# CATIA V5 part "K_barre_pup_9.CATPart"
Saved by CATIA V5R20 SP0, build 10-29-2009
Part number: barre_pup_9
Bounding box of the stored display mesh (mm): x -68.541 to -50.815, y -5.5 to 50.136, z -97.461 to 38.68
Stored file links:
  G:\Khaled_CFAO_2011\ST2M\ST2M_GR2\gcausse\Khaled\CAD_ThinkMotion\K_barre_pup_9.CATPart
  C:\Documents and Settings\gcausse\Bureau\video thinkmotio\assemblage_gcausse\pupitre_think.CATProduct
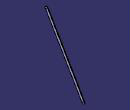
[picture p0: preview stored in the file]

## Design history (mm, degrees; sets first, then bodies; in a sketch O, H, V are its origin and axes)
Set1
  Sketch1 on Plane1, origin (-54.7303, 0, 6.7329), H (0, 1, 0), V (0.1221, 0, 0.9925)
    line L1 (-0.6657, 30.4606) -> (49.9709, -101.5846)
    arc A1 centre (47.6366, -102.4797) radius 2.5 from (49.9709, -101.5846) to (45.3024, -103.3749) cw
    point P3 (47.6366, -102.4797)
    line L2 (45.3024, -103.3749) -> (-5.3343, 28.6703)
    arc A2 centre (-3, 29.5654) radius 2.5 from (-5.3343, 28.6703) to (-0.6657, 30.4606) cw
    point P6 (-3, 29.5654)
    reference projected point E1 (47.6366, -102.4797) from Point1
    reference projected line E2 (-3, 29.5654) -> (47.6366, -102.4797) from Line1
    reference projected line E3 (-3, 29.5654) -> (47.6366, -102.4797) from Line1
    reference projected point E4 (-3, 29.5654) from Point2
    distance L1 L2 = 5
    tangency: A1 L1, L2 A1, A2 L1, A2 L2
    coincidence: P3 E1, P6 E4
    parallelism: L2 E2, L1 E3
Set2
  Plane1: linked copy from another document
  Point1: linked copy from another document
  Line1: linked copy from another document
  Point2: linked copy from another document
Body1 (main body)
  Pad1: profile Sketch1, direction (0.9925, 0, -0.1221), length -1
  Sketch2 on end face of Pad1, origin (-63.7195, 32.8057, -58.1484), H (0.1221, 0, 0.9925), V (0, 1, 0)
    point P1 (-36.9864, 14.8309)
    reference projected point E1 (-36.9864, 14.8309) from Point1
    coincidence: P1 E1
  Hole1: placed by Sketch2, at (-68.2355, 47.6366, -94.858) direction (0.9925, 0, -0.1221), diameter 1, depth 1
  Sketch3 on end face of Pad1, origin (-65.5386, 37.4083, -72.9349), H (0.1221, 0, 0.9925), V (0, 1, 0)
    point P1 (109.9568, -40.4083)
    reference projected point E1 (109.9568, -40.4083) from Point2
    coincidence: P1 E1
  Hole2: placed by Sketch3, at (-52.113, -3, 36.1992) direction (0.9925, 0, -0.1221), diameter 1, depth 1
